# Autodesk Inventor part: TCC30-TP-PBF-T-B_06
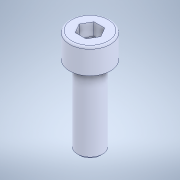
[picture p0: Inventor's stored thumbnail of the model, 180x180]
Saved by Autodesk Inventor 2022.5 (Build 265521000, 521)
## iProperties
Created: 2023-09
Part Number: TCC30-TP-PBF-T-B_06
Material: 一般
Document SubType Name: Modeling
Designer: ImaoCorp
Density: 1 g/cm^3
Appearance: 既定
Author: ImaoCorp
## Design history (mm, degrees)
feature "TCC30-TP-PBF-T-B_06"
node "ソリッド1"
